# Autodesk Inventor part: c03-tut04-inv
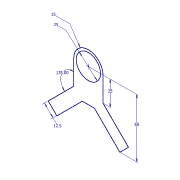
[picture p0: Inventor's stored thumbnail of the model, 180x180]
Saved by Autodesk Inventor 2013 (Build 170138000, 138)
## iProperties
Created: 2010-01
Part Number: c03-tut04-inv
Document SubType Name: Modeling
Designer: CADSoft
Density: 1 g/cm^3
Material: Generic
Author: CADSoft
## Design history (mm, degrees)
sketch "Sketch1"
  geometry: L1 (-41.161, -51.161)-(-32.322, -60); L2 (-32.322, -60)-(-6.25, -33.928); L3 (-6.25, -33.928)-(6.25, -33.928); L4 (6.25, -33.928)-(32.322, -60); L5 (32.322, -60)-(41.161, -51.161); L6 (41.161, -51.161)-(15, -25); L7 (15, -25)-(15, 0); L8 (-15, 0)-(-15, -25); L9 (-15, -25)-(-41.161, -51.161); C1 r 12.5 at (0, 0); A1 r 15 centre (0, 0) between (15, 0) and (-15, 0); 2 further points
  constraints: 18 end point, 5 equal length, 3 coincident, 3 parallel, 2 centre point, 2 perpendicular, 2 point on circle, 2 tangent, 1 horizontal, 1 vertical, 1 other
  dimensions: "d0" = 25 distance of L8.start L8.end; "d1" = 60 vertical distance of L1.end A1.centre; "d2" = 12.5 distance of L4.end L5.end; "d3" = 135 deg angle of L6 L7; "d4" = 15 radius of A1; "d5" = 25 diameter of C1
